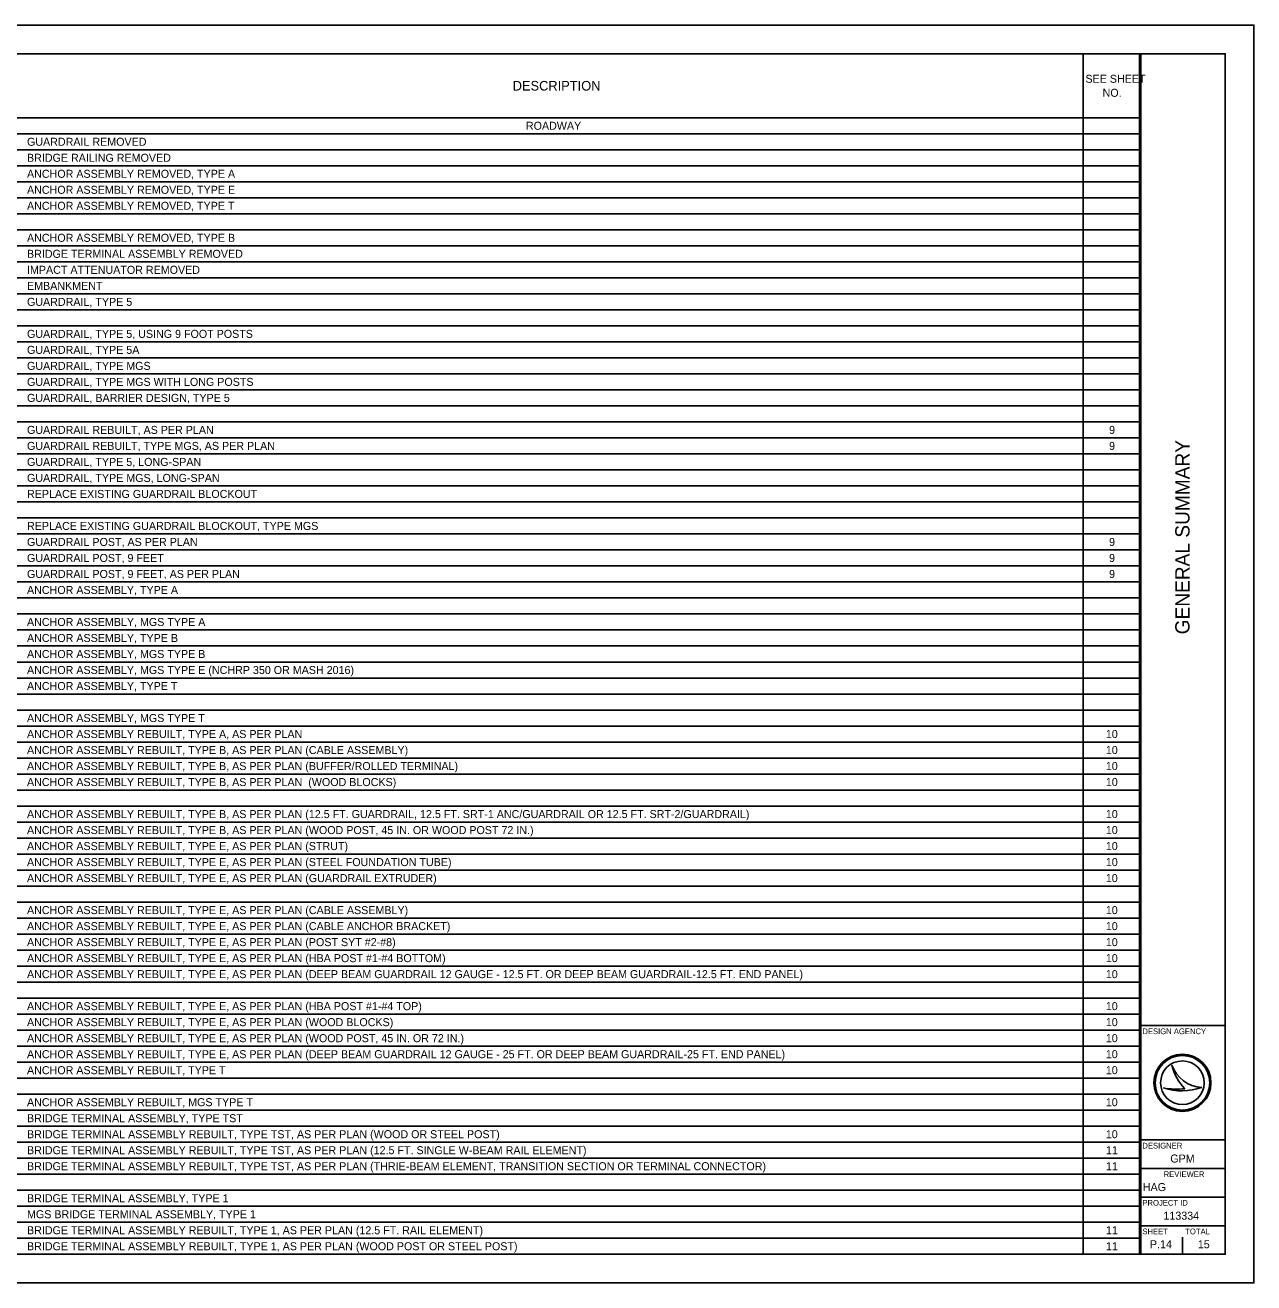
# Model space of a CAD drawing. Extents: x 0 to 34, y 0 to 22.
# Drawn here: x 12.5 to 34, y 0 to 22 of the extents above; entities that cross this region are included whole.
import ezdxf

# ---------------------------------------------------------------- set-up
doc = ezdxf.new("R2010")
doc.units = 0
for name, color, linetype in [('SH_Border', 7, 'Continuous'), ('SH_Cut_Line', 7, 'Continuous'), ('SH_Data', 7, 'Continuous'), ('SH_Text', 7, 'Continuous')]:
    doc.layers.add(name, color=color, linetype=linetype)

msp = doc.modelspace()

# ---------------------------------------------------------------- linework, layer by layer
at = {"layer": 'SH_Border'}
for p, q in [((32, 0.5), (32, 21.5)), ((32, 4.5), (33.5, 4.5)), ((32, 2.5), (33.5, 2.5)), ((32, 2), (33.5, 2)), ((32, 1.5), (33.5, 1.5)), ((32, 1), (33.5, 1))]:
    msp.add_line(p, q, dxfattribs=at)
msp.add_lwpolyline([(1.5, 21.5), (33.5, 21.5), (33.5, 0.5), (1.5, 0.5)], close=True, dxfattribs=at)
at = {"layer": 'SH_Cut_Line'}
msp.add_lwpolyline([(0, 0), (34, 0), (34, 22), (0, 22)], close=True, dxfattribs=at)
at = {"layer": 'SH_Data'}
for p, q in [((32.567, 3.81), (32.567, 3.81)), ((32.417, 3.41), (32.417, 3.41)), ((32.75, 3.5), (32.75, 3.5)), ((33.087, 3.419), (33.087, 3.419)), ((32.375, 0.675), (32.375, 0.675)), ((32.75, 0.5), (32.75, 0.8))]:
    msp.add_line(p, q, dxfattribs=at)
for radius in [0.5, 0.477, 0.477, 0.382]:
    msp.add_circle((32.75, 3.5), radius, dxfattribs=at)
for centre, radius, start, end in [((33.116, 3.998), 0.58, 198.9257, 198.9319), ((33.347, 3.97), 0.796, 191.6379, 191.6421), ((33.116, 3.998), 0.58, 198.9319, 267.1657), ((33.347, 3.97), 0.796, 191.6421, 226.0947), ((32.739, 4.37), 1.013, 251.4576, 290.0832), ((32.648, 4.654), 1.266, 259.4964, 259.4995), ((32.739, 4.37), 1.013, 251.4527, 251.4576), ((32.648, 4.654), 1.266, 259.4995, 276.6672)]:
    msp.add_arc(centre, radius, start, end, dxfattribs=at)
at = {"layer": 'SH_Text'}
for p, q in [((1.5, 21.5), (32.02, 21.5)), ((31.015, 21.5), (31.015, 0.5)), ((32.02, 21.5), (32.02, 0.5)), ((1.5, 20.38), (32.02, 20.38)), ((1.5, 20.1), (32.02, 20.1)), ((1.5, 19.82), (32.02, 19.82)), ((1.5, 19.54), (32.02, 19.54)), ((1.5, 19.26), (32.02, 19.26)), ((1.5, 18.98), (32.02, 18.98)), ((1.5, 18.7), (32.02, 18.7)), ((1.5, 18.42), (32.02, 18.42)), ((1.5, 18.14), (32.02, 18.14)), ((1.5, 17.86), (32.02, 17.86)), ((1.5, 17.58), (32.02, 17.58)), ((1.5, 17.3), (32.02, 17.3)), ((1.5, 17.02), (32.02, 17.02)), ((1.5, 16.74), (32.02, 16.74)), ((1.5, 16.46), (32.02, 16.46)), ((1.5, 16.18), (32.02, 16.18)), ((1.5, 15.9), (32.02, 15.9)), ((1.5, 15.62), (32.02, 15.62)), ((1.5, 15.34), (32.02, 15.34)), ((1.5, 15.06), (32.02, 15.06)), ((1.5, 14.78), (32.02, 14.78)), ((1.5, 14.5), (32.02, 14.5)), ((1.5, 14.22), (32.02, 14.22)), ((1.5, 13.94), (32.02, 13.94)), ((1.5, 13.66), (32.02, 13.66)), ((1.5, 13.38), (32.02, 13.38)), ((1.5, 13.1), (32.02, 13.1)), ((1.5, 12.82), (32.02, 12.82)), ((1.5, 12.54), (32.02, 12.54)), ((1.5, 12.26), (32.02, 12.26)), ((1.5, 11.98), (32.02, 11.98)), ((1.5, 11.7), (32.02, 11.7)), ((1.5, 11.42), (32.02, 11.42)), ((1.5, 11.14), (32.02, 11.14)), ((1.5, 10.86), (32.02, 10.86)), ((1.5, 10.58), (32.02, 10.58)), ((1.5, 10.3), (32.02, 10.3)), ((1.5, 10.02), (32.02, 10.02)), ((1.5, 9.74), (32.02, 9.74)), ((1.5, 9.46), (32.02, 9.46)), ((1.5, 9.18), (32.02, 9.18)), ((1.5, 8.9), (32.02, 8.9)), ((1.5, 8.62), (32.02, 8.62)), ((1.5, 8.34), (32.02, 8.34)), ((1.5, 8.06), (32.02, 8.06)), ((1.5, 7.78), (32.02, 7.78)), ((1.5, 7.5), (32.02, 7.5)), ((1.5, 7.22), (32.02, 7.22)), ((1.5, 6.94), (32.02, 6.94)), ((1.5, 6.66), (32.02, 6.66)), ((1.5, 6.38), (32.02, 6.38)), ((1.5, 6.1), (32.02, 6.1)), ((1.5, 5.82), (32.02, 5.82)), ((1.5, 5.54), (32.02, 5.54)), ((1.5, 5.26), (32.02, 5.26)), ((1.5, 4.98), (32.02, 4.98)), ((1.5, 4.7), (32.02, 4.7)), ((1.5, 4.42), (32.02, 4.42)), ((1.5, 4.14), (32.02, 4.14)), ((1.5, 3.86), (32.02, 3.86)), ((1.5, 3.58), (32.02, 3.58)), ((1.5, 3.3), (32.02, 3.3)), ((1.5, 3.02), (32.02, 3.02)), ((1.5, 2.74), (32.02, 2.74)), ((1.5, 2.46), (32.02, 2.46)), ((1.5, 2.18), (32.02, 2.18)), ((1.5, 1.9), (32.02, 1.9)), ((1.5, 1.62), (32.02, 1.62)), ((1.5, 1.34), (32.02, 1.34)), ((1.5, 1.06), (32.02, 1.06)), ((1.5, 0.78), (32.02, 0.78)), ((1.5, 0.5), (32.02, 0.5))]:
    msp.add_line(p, q, dxfattribs=at)

# ---------------------------------------------------------------- texts
at = {"layer": 'SH_Data'}
msp.add_text('GENERAL SUMMARY', height=0.25, rotation=90, dxfattribs=at).set_placement((32.875, 11.344))
for s, height, p in [('DESIGN AGENCY', 0.1, (32.05, 4.35)), ('DESIGNER', 0.1, (32.05, 2.35)), ('GPM', 0.14, (32.538, 2.105)), ('REVIEWER', 0.1, (32.422, 1.85)), ('HAG', 0.14, (32.057, 1.605)), ('PROJECT ID', 0.1, (32.05, 1.35)), ('113334', 0.14, (32.418, 1.105)), ('SHEET', 0.1, (32.05, 0.85)), ('TOTAL', 0.1, (32.8, 0.85)), ('P.14', 0.14, (32.182, 0.605)), ('15', 0.14, (33.02, 0.605))]:
    msp.add_text(s, height=height, dxfattribs=at).set_placement(p)
at = {"layer": 'SH_Text'}
for s, height, p in [('SEE SHEET ', 0.14, (31.054, 20.992)), ('DESCRIPTION', 0.168, (21.033, 20.856)), ('NO.', 0.14, (31.354, 20.747)), ('ROADWAY', 0.14, (21.264, 20.17)), ('GUARDRAIL REMOVED', 0.14, (12.535, 19.89)), ('BRIDGE RAILING REMOVED', 0.14, (12.535, 19.61)), ('ANCHOR ASSEMBLY REMOVED, TYPE A', 0.14, (12.535, 19.33)), ('ANCHOR ASSEMBLY REMOVED, TYPE E', 0.14, (12.535, 19.05)), ('ANCHOR ASSEMBLY REMOVED, TYPE T', 0.14, (12.535, 18.77)), ('ANCHOR ASSEMBLY REMOVED, TYPE B', 0.14, (12.535, 18.21)), ('BRIDGE TERMINAL ASSEMBLY REMOVED', 0.14, (12.535, 17.93)), ('IMPACT ATTENUATOR REMOVED', 0.14, (12.535, 17.65)), ('EMBANKMENT', 0.14, (12.535, 17.37)), ('GUARDRAIL, TYPE 5', 0.14, (12.535, 17.09)), ('GUARDRAIL, TYPE 5, USING 9 FOOT POSTS', 0.14, (12.535, 16.53)), ('GUARDRAIL, TYPE 5A', 0.14, (12.535, 16.25)), ('GUARDRAIL, TYPE MGS', 0.14, (12.535, 15.97)), ('GUARDRAIL, TYPE MGS WITH LONG POSTS', 0.14, (12.535, 15.69)), ('GUARDRAIL, BARRIER DESIGN, TYPE 5', 0.14, (12.535, 15.41)), ('GUARDRAIL REBUILT, AS PER PLAN', 0.14, (12.535, 14.85)), ('9', 0.14, (31.467, 14.85)), ('GUARDRAIL REBUILT, TYPE MGS, AS PER PLAN', 0.14, (12.535, 14.57)), ('9', 0.14, (31.467, 14.57)), ('GUARDRAIL, TYPE 5, LONG-SPAN', 0.14, (12.535, 14.29)), ('GUARDRAIL, TYPE MGS, LONG-SPAN', 0.14, (12.535, 14.01)), ('REPLACE EXISTING GUARDRAIL BLOCKOUT', 0.14, (12.535, 13.73)), ('REPLACE EXISTING GUARDRAIL BLOCKOUT, TYPE MGS', 0.14, (12.535, 13.17)), ('GUARDRAIL POST, AS PER PLAN', 0.14, (12.535, 12.89)), ('9', 0.14, (31.467, 12.89)), ('GUARDRAIL POST, 9 FEET', 0.14, (12.535, 12.61)), ('9', 0.14, (31.467, 12.61)), ('GUARDRAIL POST, 9 FEET, AS PER PLAN', 0.14, (12.535, 12.33)), ('9', 0.14, (31.467, 12.33)), ('ANCHOR ASSEMBLY, TYPE A', 0.14, (12.535, 12.05)), ('ANCHOR ASSEMBLY, MGS TYPE A', 0.14, (12.535, 11.49)), ('ANCHOR ASSEMBLY, TYPE B', 0.14, (12.535, 11.21)), ('ANCHOR ASSEMBLY, MGS TYPE B', 0.14, (12.535, 10.93)), ('ANCHOR ASSEMBLY, MGS TYPE E (NCHRP 350 OR MASH 2016)', 0.14, (12.535, 10.65)), ('ANCHOR ASSEMBLY, TYPE T', 0.14, (12.535, 10.37)), ('ANCHOR ASSEMBLY, MGS TYPE T', 0.14, (12.535, 9.81)), ('ANCHOR ASSEMBLY REBUILT, TYPE A, AS PER PLAN', 0.14, (12.535, 9.53)), ('10', 0.14, (31.41, 9.53)), ('ANCHOR ASSEMBLY REBUILT, TYPE B, AS PER PLAN (CABLE ASSEMBLY)', 0.14, (12.535, 9.25)), ('10', 0.14, (31.41, 9.25)), ('ANCHOR ASSEMBLY REBUILT, TYPE B, AS PER PLAN (BUFFER/ROLLED TERMINAL)', 0.14, (12.535, 8.97)), ('10', 0.14, (31.41, 8.97)), ('ANCHOR ASSEMBLY REBUILT, TYPE B, AS PER PLAN  (WOOD BLOCKS)', 0.14, (12.535, 8.69)), ('10', 0.14, (31.41, 8.69)), ('ANCHOR ASSEMBLY REBUILT, TYPE B, AS PER PLAN (12.5 FT. GUARDRAIL, 12.5 FT. SRT-1 ANC/GUARDRAIL OR 12.5 FT. SRT-2/GUARDRAIL)', 0.14, (12.535, 8.13)), ('10', 0.14, (31.41, 8.13)), ('ANCHOR ASSEMBLY REBUILT, TYPE B, AS PER PLAN (WOOD POST, 45 IN. OR WOOD POST 72 IN.)', 0.14, (12.535, 7.85)), ('10', 0.14, (31.41, 7.85)), ('ANCHOR ASSEMBLY REBUILT, TYPE E, AS PER PLAN (STRUT)', 0.14, (12.535, 7.57)), ('10', 0.14, (31.41, 7.57)), ('ANCHOR ASSEMBLY REBUILT, TYPE E, AS PER PLAN (STEEL FOUNDATION TUBE)', 0.14, (12.535, 7.29)), ('10', 0.14, (31.41, 7.29)), ('ANCHOR ASSEMBLY REBUILT, TYPE E, AS PER PLAN (GUARDRAIL EXTRUDER)', 0.14, (12.535, 7.01)), ('10', 0.14, (31.41, 7.01)), ('ANCHOR ASSEMBLY REBUILT, TYPE E, AS PER PLAN (CABLE ASSEMBLY)', 0.14, (12.535, 6.45)), ('10', 0.14, (31.41, 6.45)), ('ANCHOR ASSEMBLY REBUILT, TYPE E, AS PER PLAN (CABLE ANCHOR BRACKET)', 0.14, (12.535, 6.17)), ('10', 0.14, (31.41, 6.17)), ('ANCHOR ASSEMBLY REBUILT, TYPE E, AS PER PLAN (POST SYT #2-#8)', 0.14, (12.535, 5.89)), ('10', 0.14, (31.41, 5.89)), ('ANCHOR ASSEMBLY REBUILT, TYPE E, AS PER PLAN (HBA POST #1-#4 BOTTOM)', 0.14, (12.535, 5.61)), ('10', 0.14, (31.41, 5.61)), ('ANCHOR ASSEMBLY REBUILT, TYPE E, AS PER PLAN (DEEP BEAM GUARDRAIL 12 GAUGE - 12.5 FT. OR DEEP BEAM GUARDRAIL-12.5 FT. END PANEL)', 0.14, (12.535, 5.33)), ('10', 0.14, (31.41, 5.33)), ('ANCHOR ASSEMBLY REBUILT, TYPE E, AS PER PLAN (HBA POST #1-#4 TOP)', 0.14, (12.535, 4.77)), ('10', 0.14, (31.41, 4.77)), ('ANCHOR ASSEMBLY REBUILT, TYPE E, AS PER PLAN (WOOD BLOCKS)', 0.14, (12.535, 4.49)), ('10', 0.14, (31.41, 4.49)), ('ANCHOR ASSEMBLY REBUILT, TYPE E, AS PER PLAN (WOOD POST, 45 IN. OR 72 IN.)', 0.14, (12.535, 4.21)), ('10', 0.14, (31.41, 4.21)), ('ANCHOR ASSEMBLY REBUILT, TYPE E, AS PER PLAN (DEEP BEAM GUARDRAIL 12 GAUGE - 25 FT. OR DEEP BEAM GUARDRAIL-25 FT. END PANEL)', 0.14, (12.535, 3.93)), ('10', 0.14, (31.41, 3.93)), ('ANCHOR ASSEMBLY REBUILT, TYPE T', 0.14, (12.535, 3.65)), ('10', 0.14, (31.41, 3.65)), ('ANCHOR ASSEMBLY REBUILT, MGS TYPE T', 0.14, (12.535, 3.09)), ('10', 0.14, (31.41, 3.09)), ('BRIDGE TERMINAL ASSEMBLY, TYPE TST', 0.14, (12.535, 2.81)), ('BRIDGE TERMINAL ASSEMBLY REBUILT, TYPE TST, AS PER PLAN (WOOD OR STEEL POST)', 0.14, (12.535, 2.53)), ('10', 0.14, (31.41, 2.53)), ('BRIDGE TERMINAL ASSEMBLY REBUILT, TYPE TST, AS PER PLAN (12.5 FT. SINGLE W-BEAM RAIL ELEMENT)', 0.14, (12.535, 2.25)), ('11', 0.14, (31.412, 2.25)), ('BRIDGE TERMINAL ASSEMBLY REBUILT, TYPE TST, AS PER PLAN (THRIE-BEAM ELEMENT, TRANSITION SECTION OR TERMINAL CONNECTOR)', 0.14, (12.535, 1.97)), ('11', 0.14, (31.412, 1.97)), ('BRIDGE TERMINAL ASSEMBLY, TYPE 1', 0.14, (12.535, 1.41)), ('MGS BRIDGE TERMINAL ASSEMBLY, TYPE 1', 0.14, (12.535, 1.13)), ('BRIDGE TERMINAL ASSEMBLY REBUILT, TYPE 1, AS PER PLAN (12.5 FT. RAIL ELEMENT)', 0.14, (12.535, 0.85)), ('11', 0.14, (31.412, 0.85)), ('BRIDGE TERMINAL ASSEMBLY REBUILT, TYPE 1, AS PER PLAN (WOOD POST OR STEEL POST)', 0.14, (12.535, 0.57)), ('11', 0.14, (31.412, 0.57))]:
    msp.add_text(s, height=height, dxfattribs=at).set_placement(p)

doc.saveas('drawing.dxf')
